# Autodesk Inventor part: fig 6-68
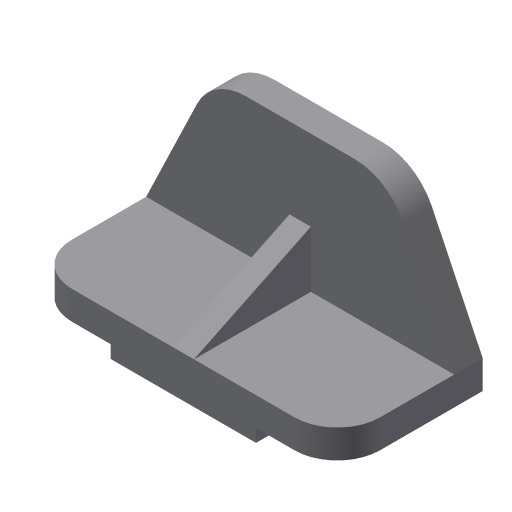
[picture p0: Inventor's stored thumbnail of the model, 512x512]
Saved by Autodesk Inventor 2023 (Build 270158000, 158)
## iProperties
Created: 2001-12
Part Number: fig 6-68
Document SubType Name: Modeling
Designer: Renu Muthoo
Density: 1 g/cm^3
Material: Generic
Appearance: Default
Control State: 0
Master: False
Checked Out: False
Shininess: 77.0
Length Units: 11269
Angle Units: 11279
Time Units: 11290
Mass Units: 11283
Length Display Precision: 3
Angle Display Precision: 2
Density: 0.0
Volumn: 0.0
Area: 0.0
PropertySet Name: Model Information
Author: Renu Muthoo
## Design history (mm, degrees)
node "Sketch1"
sketch "Sketch2"
  geometry: L1 (-67.219, 19.116)-(148.781, 19.116); L2 (148.781, 19.116)-(148.781, -0.884); L3 (-67.219, -0.884)-(-67.219, 19.116); L4 (-10.219, -0.884)-(-10.219, -9.884); L5 (-10.219, -9.884)-(91.781, -9.884); L6 (91.781, -9.884)-(91.781, -0.884); L7 (148.781, -0.884)-(91.781, -0.884); L8 (-10.219, -0.884)-(-67.219, -0.884)
  constraints: 16 end point, 5 parallel, 4 perpendicular, 2 equal length, 1 horizontal
  dimensions: "d0" = 102 distance of L4.end L5.end; "d1" = 57 distance of L4.start L3.start; "d2" = 29 distance between parallel lines of L1 L5; "d3" = 20 distance of L1.end L2.end
extrude "Extrusion1" new body sketch "Sketch2" distance "d4" = 102; taper "d5" = 0 deg
sketch "Sketch3"
  geometry: L1 (67.219, -19.116)-(-148.781, -19.116) reference; L2 (67.219, -19.116)-(31.475, -93.564); L3 (-2.781, -115.116)-(-78.781, -115.116); L4 (-113.038, -93.564)-(-148.781, -19.116); A1 r 38 centre (-2.781, -77.116) between (-2.781, -115.116) and (31.475, -93.564); A2 r 38 centre (-78.781, -77.116) between (-113.038, -93.564) and (-78.781, -115.116)
  constraints: 6 end point, 4 point on circle, 4 tangent, 2 centre point, 1 equal length, 1 equal radius, 1 parallel
  dimensions: "d6" = 96 distance between parallel lines of L3 L1; "d7" = 38 radius of A1; "d8" = 76 distance of A2.centre A1.centre
extrude "Extrusion2" join sketch "Sketch3" distance "d9" = 20; taper "d10" = 0 deg
fillet "Fillet1" dims "d11" = 30
workplane "Work Plane1"
sketch "Sketch7"
  geometry: L1 (0, -82)-(-39.557, 0)
  constraints: 2 end point
feature "Rib4" sketch "Sketch7" dims "d37" = 1, "d38" = 15, "d39" = 0
body "Solid1"
other parameters: "d12" = -108
